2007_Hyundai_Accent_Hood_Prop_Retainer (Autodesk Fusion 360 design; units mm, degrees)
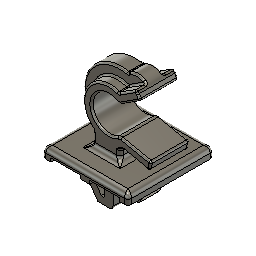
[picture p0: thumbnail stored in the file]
sketch "Sketch1" plane through (0, 0, 0) normal (0, 0, 1) x axis (1, 0, 0)
  line L1 (9.7855, -4.7015) -> (2.4047, -3.1572)
  line L2 (7.3657, 6.411) -> (2.3574, 3.1928)
  line L3 (6.2929, 8.0804) -> (2.2776, 5.5002)
  line L4 (9.3792, -6.6438) -> (2.7814, -5.2634)
  line L5 (8.8915, -8.9746) -> (3.0564, -7.7537)
  line L6 (5.0056, 10.0837) -> (1.9305, 8.1077)
  line L7 (7.3657, 6.411) -> (6.2929, 8.0804)
  line L8 (6.2929, 8.0804) -> (5.0056, 10.0837)
  line L9 (9.3792, -6.6438) -> (8.8915, -8.9746)
  line L10 (9.7855, -4.7015) -> (9.3792, -6.6438)
  line L11 (9.9219, -8.3344) -> (-9.9219, -8.3344)
  line L12 (9.9219, -9.9219) -> (9.9219, -8.3344)
  line L13 (-9.9219, -9.9219) -> (9.9219, -9.9219)
  line L14 (-9.9219, -8.3344) -> (-9.9219, -9.9219)
  line L15 (7.9375, -9.9219) -> (9.9219, -9.9219)
  line L16 (7.9375, -10.7156) -> (7.9375, -9.9219)
  line L17 (9.9219, -10.7156) -> (7.9375, -10.7156)
  line L18 (9.9219, -9.9219) -> (9.9219, -10.7156)
  line L19 (0.9922, -9.9219) -> (-0.9922, -9.9219)
  line L20 (0.9922, -10.7156) -> (0.9922, -9.9219)
  line L21 (-0.9922, -10.7156) -> (0.9922, -10.7156)
  line L22 (-0.9922, -9.9219) -> (-0.9922, -10.7156)
  line L23 (-7.9375, -9.9219) -> (-9.9219, -9.9219)
  line L24 (-7.9375, -10.7156) -> (-7.9375, -9.9219)
  line L25 (-9.9219, -10.7156) -> (-7.9375, -10.7156)
  line L26 (-9.9219, -9.9219) -> (-9.9219, -10.7156)
  line L27 (-3.5719, -4.7625) -> (2.6318, -4.7625)
  line L28 (-3.5719, -8.3344) -> (-3.5719, -4.7625)
  line L29 (2.6318, -8.3344) -> (-3.5719, -8.3344)
  line L30 (2.6318, -4.7625) -> (2.6318, -8.3344)
  line L31 (4.5641, -9.9219) -> (0, -9.9219)
  line L32 (4.5641, -12.3031) -> (4.5641, -9.9219)
  line L33 (0, -12.3031) -> (4.5641, -12.3031)
  line L34 (0, -9.9219) -> (0, -12.3031)
  line L35 (-0.9922, -9.9219) -> (0.9922, -9.9219)
  line L36 (-0.9922, -18.6531) -> (-0.9922, -9.9219)
  line L37 (0.9922, -18.6531) -> (-0.9922, -18.6531)
  line L38 (0.9922, -9.9219) -> (0.9922, -18.6531)
  line L39 (-3.0066, -11.5094) -> (-4.0063, -13.8906)
  line L40 (-4.8057, -11.5094) -> (-5.7562, -13.7734)
  line L41 (-4.8057, -11.5094) -> (-3.0066, -11.5094)
  line L42 (-2.5168, -18.6531) -> (-5.7562, -13.7734)
  line L43 (-0.9922, -18.0331) -> (-4.0063, -13.8906)
  line L44 (-0.9922, -18.6531) -> (-2.5168, -18.6531)
  arc A1 centre (0, 0) radius 3.9688 clockwise from (2.4047, -3.1572) to (2.3574, 3.1928)
  arc A2 centre (0, 0) radius 5.9531 clockwise from (2.7814, -5.2634) to (2.2776, 5.5002)
  arc A3 centre (0, 0) radius 8.3344 clockwise from (3.0564, -7.7537) to (1.9305, 8.1077)
  point P1 (0, 0)
  point P2 (0, 0)
  point P24 (-0.9922, -9.9219)
  point P32 (-3.5719, -8.3344)
  point P31 (-3.5719, -4.7625)
  point P35 (0, -9.9219)
  point P27 (-0.9922, -10.7156)
  point P47 (-4.8057, -11.5094)
  point P45 (-4.8057, -11.5094)
  point P48 (-0.9922, -18.0331)
  point P3 (2.4047, -3.1572)
  point P5 (2.3574, 3.1928)
  point P4 (9.7855, -4.7015)
  point P6 (7.3657, 6.411)
  point P18 (9.9219, -8.3344)
  point P23 (9.9219, -10.7156)
  point P26 (0.9922, -10.7156)
  point P17 (-9.9219, -8.3344)
  point P30 (-9.9219, -10.7156)
  point P29 (-7.9375, -10.7156)
  point P22 (7.9375, -10.7156)
  point P9 (0, 0)
  point P19 (9.9219, -9.9219)
  point P36 (4.5641, -9.9219)
  point P37 (4.5641, -12.3031)
  point P14 (0, 0)
  point P39 (-0.9922, -9.9219)
  point P40 (-0.9922, -18.6531)
  point P42 (-4.0063, -13.8906)
  point P43 (-3.0066, -11.5094)
  point P33 (2.6318, -8.3344)
  point P34 (2.6318, -4.7625)
  perpendicular L2 L7
  perpendicular L3 L8
  perpendicular L4 L9
  perpendicular L1 L10
  coincident P1 P2
  horizontal L11
  vertical L12
  horizontal L13
  vertical L14
  horizontal L15
  vertical L16
  horizontal L17
  vertical L18
  horizontal L19
  vertical L20
  horizontal L21
  vertical L22
  coincident L13 P24
  horizontal L23
  vertical L24
  horizontal L25
  vertical L26
  horizontal L27
  vertical L28
  horizontal L29
  vertical L30
  coincident L11 P32
  coincident A2 P31
  horizontal L31
  vertical L32
  horizontal L33
  vertical L34
  midpoint L13 P35
  horizontal L35
  vertical L36
  horizontal L37
  vertical L38
  coincident P27 L36
  coincident L40 P47
  perpendicular L36 L41
  parallel L39 L40
  coincident P45 P47
  coincident L36 P48
  collinear L37 L44
  dimension "d1" diameter A1 = 7.9375 (= "19/64  + 1/64")
  dimension "d2" distance P3 P5 = 6.35 (= "1/4")
  dimension "d3" distance P3 P4 = 7.5406 (= "19/64")
  dimension "d4" distance P5 P6 = 5.9531 (= "15/64")
  dimension "d5" distance P4 P6 = 11.1125 (= "7/16")
  dimension "d6" = -1.9844 (= "-5/64")
  dimension "d7" = 4.3656 (= "5/64  + 3/32")
  dimension "d12" distance L11 L13 = 1.5875 (= "1/16")
  dimension "d13" distance P18 P23 = 2.3813 (= "3/32")
  dimension "d14" distance L11 P26 = 2.3813 (= "d13")
  dimension "d15" distance P17 P30 = 2.3813 (= "d14")
  dimension "d16" distance P29 P30 = 1.9844 (= "5/64")
  dimension "d17" distance P26 P27 = 1.9844 (= "5/64")
  dimension "d18" distance P22 P23 = 1.9844 (= "5/64")
  dimension "d19" distance P17 P18 = 19.8438 (= "25/32")
  dimension "d20" distance P2 P26 = 0.9922 (= "d17 / 2")
  dimension "d21" distance P9 P19 = 9.9219 (= "d19 / 2")
  dimension "d24" distance P36 P37 = 2.3813 (= "3/32")
  dimension "d25" distance P27 P37 = 5.5563 (= "7/32")
  dimension "d27" distance P14 P31 = 3.5719 (= "9/64")
  dimension "d28" distance P39 P40 = 8.7313 (= "11/32")
  dimension "d32" distance P40 P42 = 4.7625 (= "3/16")
  dimension "d33" distance L13 P43 = 1.5875 (= "1/16")
  dimension "d52" distance P33 P34 = 3.5719 (= "9/64")
extrude "Extrude1" new body sketch "Sketch1" profile of A1 L1 L2 L3 A2 L4 A3 L7 L10 L11 L27 L28 L29 L30 distance 8.9297 (= "( 0.3515625   )")
extrude "Extrude2" add sketch "Sketch1" profile of L3 A2 A3 L6 L8 L28 L30 distance 3.9688 (= "5/32")
extrude "Extrude3" add sketch "Sketch1" profile of L11 L12 L13 L14 L15 L16 L17 L18 L19 L20 L21 L22 L23 L24 L25 L26 L29 distance 19.8438 (= "25/32")
extrude "Extrude4" new body sketch "Sketch1" profile of L13 L20 L21 L31 L32 L33 L34 L36 L37 L38 L39 L40 L41 to an object
sketch "Sketch2" plane through (0, 0, 4.4648) normal (0, 0, 1) x axis (1, 0, 0)
  line L1 (0.9922, -10.7156) -> (0.9922, -9.9219)
  line L2 (-0.9922, -10.7156) -> (0.9922, -10.7156)
  line L3 (-0.9922, -18.0331) -> (-0.9922, -10.7156)
  line L4 (0.9922, -18.6531) -> (-2.5168, -18.6531)
  line L5 (0.9922, -12.3031) -> (0.9922, -18.6531)
  line L6 (4.5641, -12.3031) -> (0.9922, -12.3031)
  line L7 (4.5641, -9.9219) -> (4.5641, -12.3031)
  line L8 (0.9922, -9.9219) -> (4.5641, -9.9219)
  line L9 (-4.0063, -13.8906) -> (-0.9922, -18.0331)
  line L10 (-3.0066, -11.5094) -> (-4.0063, -13.8906)
  line L11 (-4.8057, -11.5094) -> (-3.0066, -11.5094)
  line L12 (-5.7562, -13.7734) -> (-4.8057, -11.5094)
  line L13 (-2.5168, -18.6531) -> (-5.7562, -13.7734)
split "Split1"
chamfer "Chamfer1" distance 0.3969 (= "1/64") distance 5.9531 (= "15/64")
combine "Combine1"
mirror "Mirror1" mirrorStitchTolerance 0 (= "0")
mirror "Mirror2" mirrorStitchTolerance 0 (= "0")
fillet "Fillet1" radius 1.1906 (= "3/64")
fillet "Fillet2" radius 3.175 (= "1/8")
fillet "Fillet3" radius 0.7937 (= "1/32")
combine "Combine2"
fillet "Fillet5" radius 0.3969 (= "1/64")
fillet "Fillet6" radius 0.3969 (= "1/64")
fillet "Fillet7" radius 1.1906 (= "3/64")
